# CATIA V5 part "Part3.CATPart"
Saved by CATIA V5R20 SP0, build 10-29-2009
Part number: Part3
Bounding box of the stored display mesh (mm): x -9 to 9, y -17.196 to 17.804, z -250 to 282.49
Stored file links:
  E:\Ehsan\Catia\Tamrin\Digital Mockup\3\Part3.CATPart
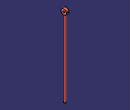
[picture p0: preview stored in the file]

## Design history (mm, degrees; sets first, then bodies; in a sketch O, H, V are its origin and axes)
Body1 (main body)
  Sketch1 on xy-plane, origin (0, 0, 0), H (1, 0, 0), V (0, 1, 0)
    circle A1 centre (0, 0) radius 9
    radius A1 = 9
  Pad1: profile Sketch1, direction (0, 0, 1), length 250, mirrored extent
  Sketch2 on yz-plane, origin (0, 0, 0), H (0, 1, 0), V (0, 0, 1)
    circle A1 centre (0, 265) radius 6
    point P1 (0, 265)
    reference projected line E1 (-9, 250) -> (9, 250) from edge [face of Pad1 from Sketch1.A1 | end face of Pad1]
    circle A2 centre (0.3043, 265) radius 17.5
    radius A1 = 6
    distance P1 E1 = 15
    radius A2 = 17.5
    coincidence: P1 V
  Pad2: profile Sketch2, direction (1, 0, 0), length 9, mirrored extent
  Fillet1: radius 3, on edge [face of Pad1 from Sketch1.A1 | face of Pad2 from Sketch2.A2]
